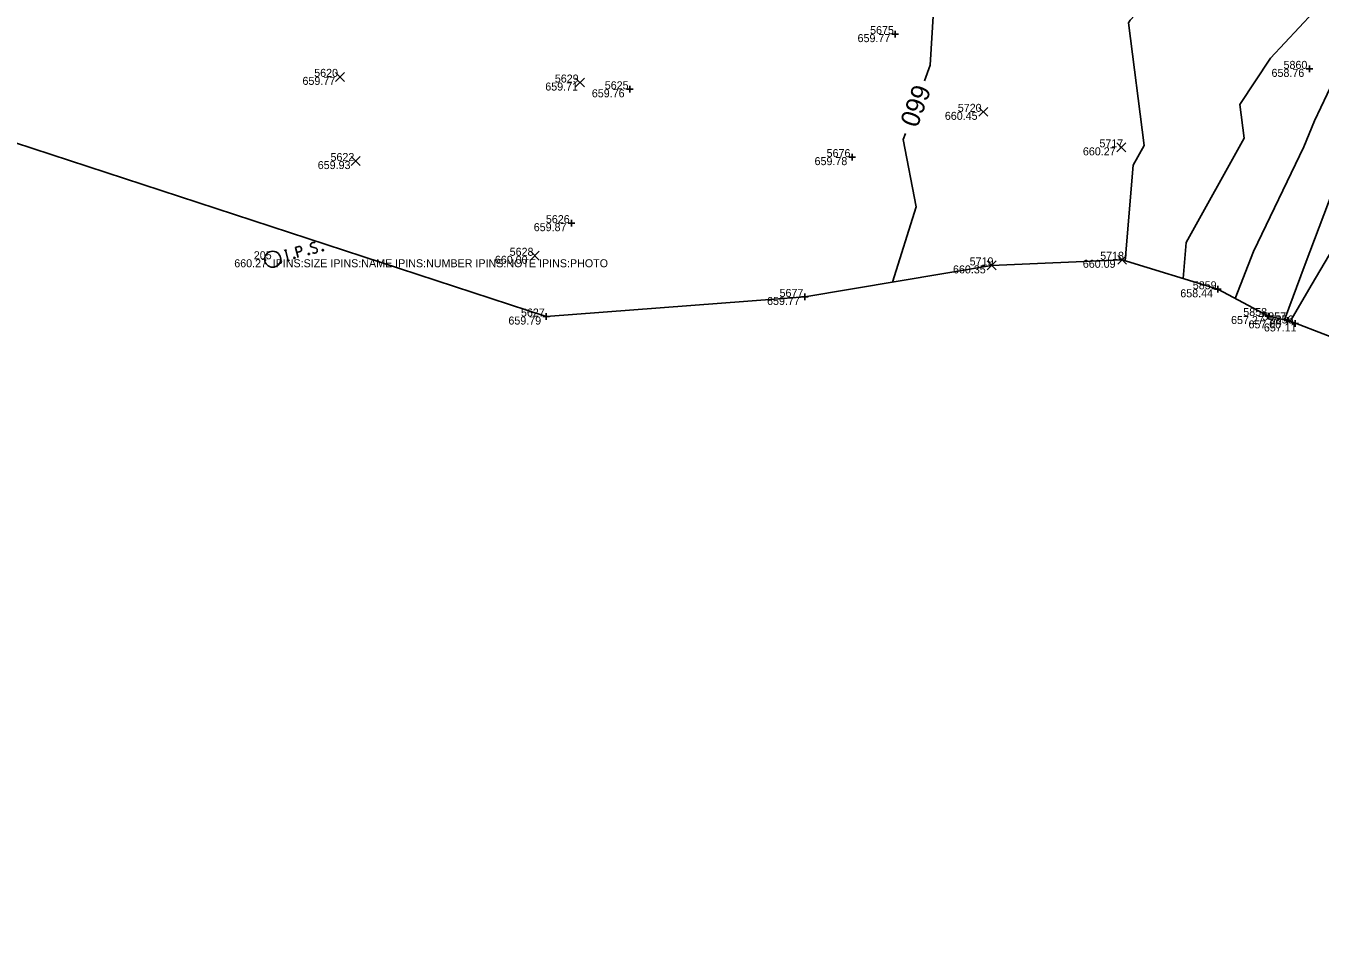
# Model space of a CAD drawing. Extents: x 2129350 to 2137777, y 657588 to 659885.
# Drawn here: x 2131820.1 to 2132014.2, y 658068.2 to 658204.8 of the extents above; entities that cross this region are included whole.
import ezdxf

# ---------------------------------------------------------------- set-up
doc = ezdxf.new("R2010")
doc.units = 0
for name, color, linetype in [('DT_X_Contour_Major', 7, 'Continuous'), ('DT_X_Contour_Minor', 7, 'Continuous'), ('DT_X_TIN_Hull', 7, 'Continuous'), ('SV_P_Mon_Cells_Set', 7, 'Continuous'), ('SV_X_Random_Point', 7, 'Continuous'), ('SV_X_Shot_Marker', 7, 'Continuous'), ('SV_X_Text_Comment', 7, 'Continuous'), ('SV_X_Text_Elevation', 7, 'Continuous'), ('SV_X_Text_Name', 7, 'Continuous')]:
    doc.layers.add(name, color=color, linetype=linetype)

msp = doc.modelspace()

# ---------------------------------------------------------------- linework, layer by layer
at = {"layer": 'DT_X_Contour_Major'}
for points in [[(2131984.96, 658169.6), (2131986.17, 658183.96), (2131987.79, 658186.87), (2131985.44, 658205.27), (2131985.72, 658205.69), (2131987.74, 658207.85), (2131983.72, 658215.22), (2131979.07, 658223.95), (2131964.25, 658221.15), (2131960.19, 658214.97), (2131956.23, 658207.09), (2131955.73, 658198.94), (2131954.87, 658196.58)], [(2131952, 658188.69), (2131951.67, 658187.78), (2131953.59, 658177.71), (2131950.06, 658166.4)]]:
    msp.add_lwpolyline(points, dxfattribs=at)
at = {"layer": 'DT_X_Contour_Minor'}
for points in [[(2132015.34, 658209.21), (2132006.72, 658199.97), (2132002.16, 658193.03), (2132002.8, 658187.99), (2131994.1, 658172.32), (2131993.64, 658166.94)], [(2132016.17, 658196.58), (2132013.32, 658190.6), (2132011.75, 658186.69), (2132004.2, 658170.97), (2132001.44, 658163.97)], [(2132017.56, 658183.89), (2132011.92, 658169.07), (2132008.85, 658160.76)], [(2132021.12, 658179.96), (2132012.97, 658166.17), (2132009.71, 658160.52)]]:
    msp.add_lwpolyline(points, dxfattribs=at)
at = {"layer": 'DT_X_TIN_Hull'}
for points in [[(2131478.92, 658068.21), (2131503.79, 658070.83), (2131528.65, 658073.45), (2131573.86, 658152.61), (2131617.57, 658130.95), (2131669.63, 658175.29), (2131715.13, 658184.95), (2131768.27, 658182.72), (2131818.39, 658187.33), (2131898.11, 658161.24), (2131936.89, 658164.18)], [(2131936.89, 658164.18), (2131964.92, 658168.91), (2131984.49, 658169.75), (2131998.86, 658165.33), (2132006.44, 658161.32), (2132009.28, 658160.67), (2132010.51, 658160.24), (2132022.93, 658155.45), (2132058.27, 658177.08), (2132116.06, 658178.71), (2132163.22, 658178.82), (2132167.87, 658178.85), (2132213.87, 658182.33)]]:
    msp.add_lwpolyline(points, dxfattribs=at)
at = {"layer": 'SV_P_Mon_Cells_Set'}
for points in [[(2131863.45, 658172.3), (2131863.42, 658172.32), (2131863.38, 658172.34), (2131863.27, 658172.35), (2131863.15, 658172.34), (2131863.07, 658172.32), (2131863.03, 658172.31), (2131862.91, 658172.23), (2131862.81, 658172.13), (2131862.76, 658172.01), (2131862.77, 658171.91), (2131862.79, 658171.83), (2131862.84, 658171.74), (2131862.95, 658171.68), (2131863.63, 658171.48), (2131863.7, 658171.44), (2131863.73, 658171.4), (2131863.77, 658171.33), (2131863.79, 658171.26), (2131863.8, 658171.19), (2131863.81, 658171.13), (2131863.8, 658171.07), (2131863.79, 658171.01), (2131863.78, 658170.97), (2131863.76, 658170.93), (2131863.74, 658170.89), (2131863.7, 658170.86), (2131863.67, 658170.84), (2131863.58, 658170.8), (2131863.43, 658170.76), (2131863.33, 658170.75), (2131863.17, 658170.8), (2131863.06, 658170.85)], [(2131858.84, 658171.14), (2131859.18, 658171.24)], [(2131859.44, 658169.65), (2131859.01, 658171.19)], [(2131860.95, 658170.07), (2131860.52, 658171.61), (2131861.03, 658171.75), (2131861.08, 658171.75), (2131861.16, 658171.75), (2131861.2, 658171.73), (2131861.24, 658171.72), (2131861.3, 658171.67), (2131861.35, 658171.62), (2131861.4, 658171.53), (2131861.44, 658171.38), (2131861.44, 658171.33), (2131861.44, 658171.25), (2131861.42, 658171.15), (2131861.39, 658171.1), (2131861.36, 658171.07), (2131861.32, 658171.03), (2131861.24, 658171), (2131860.73, 658170.85)], [(2131862.47, 658170.71), (2131862.52, 658170.73), (2131862.56, 658170.71), (2131862.61, 658170.67), (2131862.62, 658170.61), (2131862.61, 658170.55), (2131862.58, 658170.52), (2131862.53, 658170.51), (2131862.49, 658170.52), (2131862.44, 658170.56), (2131862.43, 658170.62), (2131862.45, 658170.68), (2131862.47, 658170.71)], [(2131864.57, 658171.3), (2131864.63, 658171.31), (2131864.67, 658171.29), (2131864.71, 658171.25), (2131864.73, 658171.19), (2131864.71, 658171.14), (2131864.68, 658171.1), (2131864.63, 658171.09), (2131864.59, 658171.1), (2131864.55, 658171.14), (2131864.53, 658171.2), (2131864.55, 658171.26), (2131864.57, 658171.3)], [(2131859.27, 658169.6), (2131859.61, 658169.69)], [(2131860.3, 658170.11), (2131860.36, 658170.12), (2131860.4, 658170.11), (2131860.44, 658170.07), (2131860.46, 658170.01), (2131860.44, 658169.95), (2131860.41, 658169.92), (2131860.36, 658169.9), (2131860.32, 658169.92), (2131860.28, 658169.96), (2131860.26, 658170.02), (2131860.28, 658170.08), (2131860.3, 658170.11)]]:
    msp.add_lwpolyline(points, dxfattribs=at)
msp.add_circle((2131857.11, 658169.83), 1.2, dxfattribs=at)
at = {"layer": 'SV_X_Random_Point'}
for p, q in [((2131866.55, 658196.5), (2131867.88, 658197.84)), ((2131866.55, 658197.84), (2131867.88, 658196.5)), ((2131902.53, 658195.66), (2131903.87, 658196.99)), ((2131902.53, 658196.99), (2131903.87, 658195.66)), ((2131963.02, 658191.26), (2131964.35, 658192.6)), ((2131963.02, 658192.6), (2131964.35, 658191.26)), ((2131983.7, 658185.95), (2131985.03, 658187.28)), ((2131983.7, 658187.28), (2131985.03, 658185.95)), ((2131868.88, 658183.88), (2131870.21, 658185.22)), ((2131868.88, 658185.22), (2131870.21, 658183.88)), ((2131895.76, 658169.68), (2131897.09, 658171.02)), ((2131895.76, 658171.02), (2131897.09, 658169.68)), ((2131983.83, 658169.08), (2131985.16, 658170.41)), ((2131983.83, 658170.41), (2131985.16, 658169.08)), ((2131964.25, 658168.24), (2131965.59, 658169.58)), ((2131964.25, 658169.58), (2131965.59, 658168.24))]:
    msp.add_line(p, q, dxfattribs=at)
at = {"layer": 'SV_X_Shot_Marker'}
for p, q in [((2131949.96, 658203.58), (2131950.96, 658203.58)), ((2131950.46, 658204.08), (2131950.46, 658203.08)), ((2131950.46, 658203.58), (2131950.46, 658203.58)), ((2132012.09, 658198.37), (2132013.09, 658198.37)), ((2132012.59, 658198.87), (2132012.59, 658197.87)), ((2132012.59, 658198.37), (2132012.59, 658198.37)), ((2131910.68, 658195.81), (2131910.68, 658194.81)), ((2131910.18, 658195.31), (2131911.18, 658195.31)), ((2131910.68, 658195.31), (2131910.68, 658195.31)), ((2131943.52, 658185.14), (2131944.52, 658185.14)), ((2131944.02, 658185.64), (2131944.02, 658184.64)), ((2131944.02, 658185.14), (2131944.02, 658185.14)), ((2131901.42, 658175.24), (2131902.42, 658175.24)), ((2131901.92, 658175.74), (2131901.92, 658174.74)), ((2131901.92, 658175.24), (2131901.92, 658175.24)), ((2131936.89, 658164.68), (2131936.89, 658163.68)), ((2131998.36, 658165.33), (2131999.36, 658165.33)), ((2131998.86, 658165.83), (2131998.86, 658164.83)), ((2131998.86, 658165.33), (2131998.86, 658165.33)), ((2131936.39, 658164.18), (2131937.39, 658164.18)), ((2131936.89, 658164.18), (2131936.89, 658164.18)), ((2131897.61, 658161.24), (2131898.61, 658161.24)), ((2131898.11, 658161.74), (2131898.11, 658160.74)), ((2131898.11, 658161.24), (2131898.11, 658161.24)), ((2132005.94, 658161.32), (2132006.94, 658161.32)), ((2132006.44, 658161.82), (2132006.44, 658160.82)), ((2132006.44, 658161.32), (2132006.44, 658161.32)), ((2132008.78, 658160.67), (2132009.78, 658160.67)), ((2132009.28, 658161.17), (2132009.28, 658160.17)), ((2132009.28, 658160.67), (2132009.28, 658160.67)), ((2132010.46, 658160.71), (2132010.46, 658159.71)), ((2132009.96, 658160.21), (2132010.96, 658160.21)), ((2132010.46, 658160.21), (2132010.46, 658160.21))]:
    msp.add_line(p, q, dxfattribs=at)

# ---------------------------------------------------------------- texts
at = {"layer": 'DT_X_Contour_Major'}
msp.add_text('660', height=2.8, rotation=250.0331, dxfattribs=at).set_placement((2131953.27, 658196.26))
at = {"layer": 'SV_X_Text_Comment'}
msp.add_text('IPINS:SIZE IPINS:NAME IPINS:NUMBER IPINS:NOTE IPINS:PHOTO', height=1.2, dxfattribs=at).set_placement((2131857.11, 658168.63))
at = {"layer": 'SV_X_Text_Elevation'}
for s, p in [('659.77', (2131944.82, 658202.38)), ('658.76', (2132006.9, 658197.17)), ('659.77', (2131861.58, 658195.97)), ('659.71', (2131897.99, 658195.12)), ('659.76', (2131904.97, 658194.11)), ('660.45', (2131957.91, 658190.73)), ('660.27', (2131978.61, 658185.41)), ('659.93', (2131863.87, 658183.35)), ('659.78', (2131938.37, 658183.94)), ('659.87', (2131896.26, 658174.04)), ('660.00', (2131890.43, 658169.15)), ('660.27', (2131851.35, 658168.63)), ('660.35', (2131959.13, 658167.71)), ('660.09', (2131978.6, 658168.55)), ('658.44', (2131993.22, 658164.13)), ('659.77', (2131931.25, 658162.98)), ('659.79', (2131892.46, 658160.04)), ('657.27', (2132000.83, 658160.12)), ('657.00', (2132003.44, 658159.47)), ('657.11', (2132005.75, 658159.01))]:
    msp.add_text(s, height=1.2, dxfattribs=at).set_placement(p)
at = {"layer": 'SV_X_Text_Name'}
for s, p in [('5675', (2131946.7, 658203.58)), ('5860', (2132008.7, 658198.37)), ('5620', (2131863.34, 658197.17)), ('5629', (2131899.42, 658196.32)), ('5625', (2131906.91, 658195.31)), ('5720', (2131959.85, 658191.93)), ('5676', (2131940.18, 658185.14)), ('5717', (2131981.09, 658186.61)), ('5622', (2131865.78, 658184.55)), ('5626', (2131898.08, 658175.24)), ('205', (2131854.28, 658169.83)), ('5628', (2131892.65, 658170.35)), ('5718', (2131981.2, 658169.75)), ('5719', (2131961.63, 658168.91)), ('5859', (2131995.09, 658165.33)), ('5677', (2131933.12, 658164.18)), ('5627', (2131894.34, 658161.24)), ('5858', (2132002.66, 658161.32)), ('5857', (2132005.51, 658160.67)), ('5856', (2132006.62, 658160.21))]:
    msp.add_text(s, height=1.2, dxfattribs=at).set_placement(p)

doc.saveas('drawing.dxf')
